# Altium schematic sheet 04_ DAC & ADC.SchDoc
size 420 x 297 mm; SheetNumber: 4; SheetTotal: 4
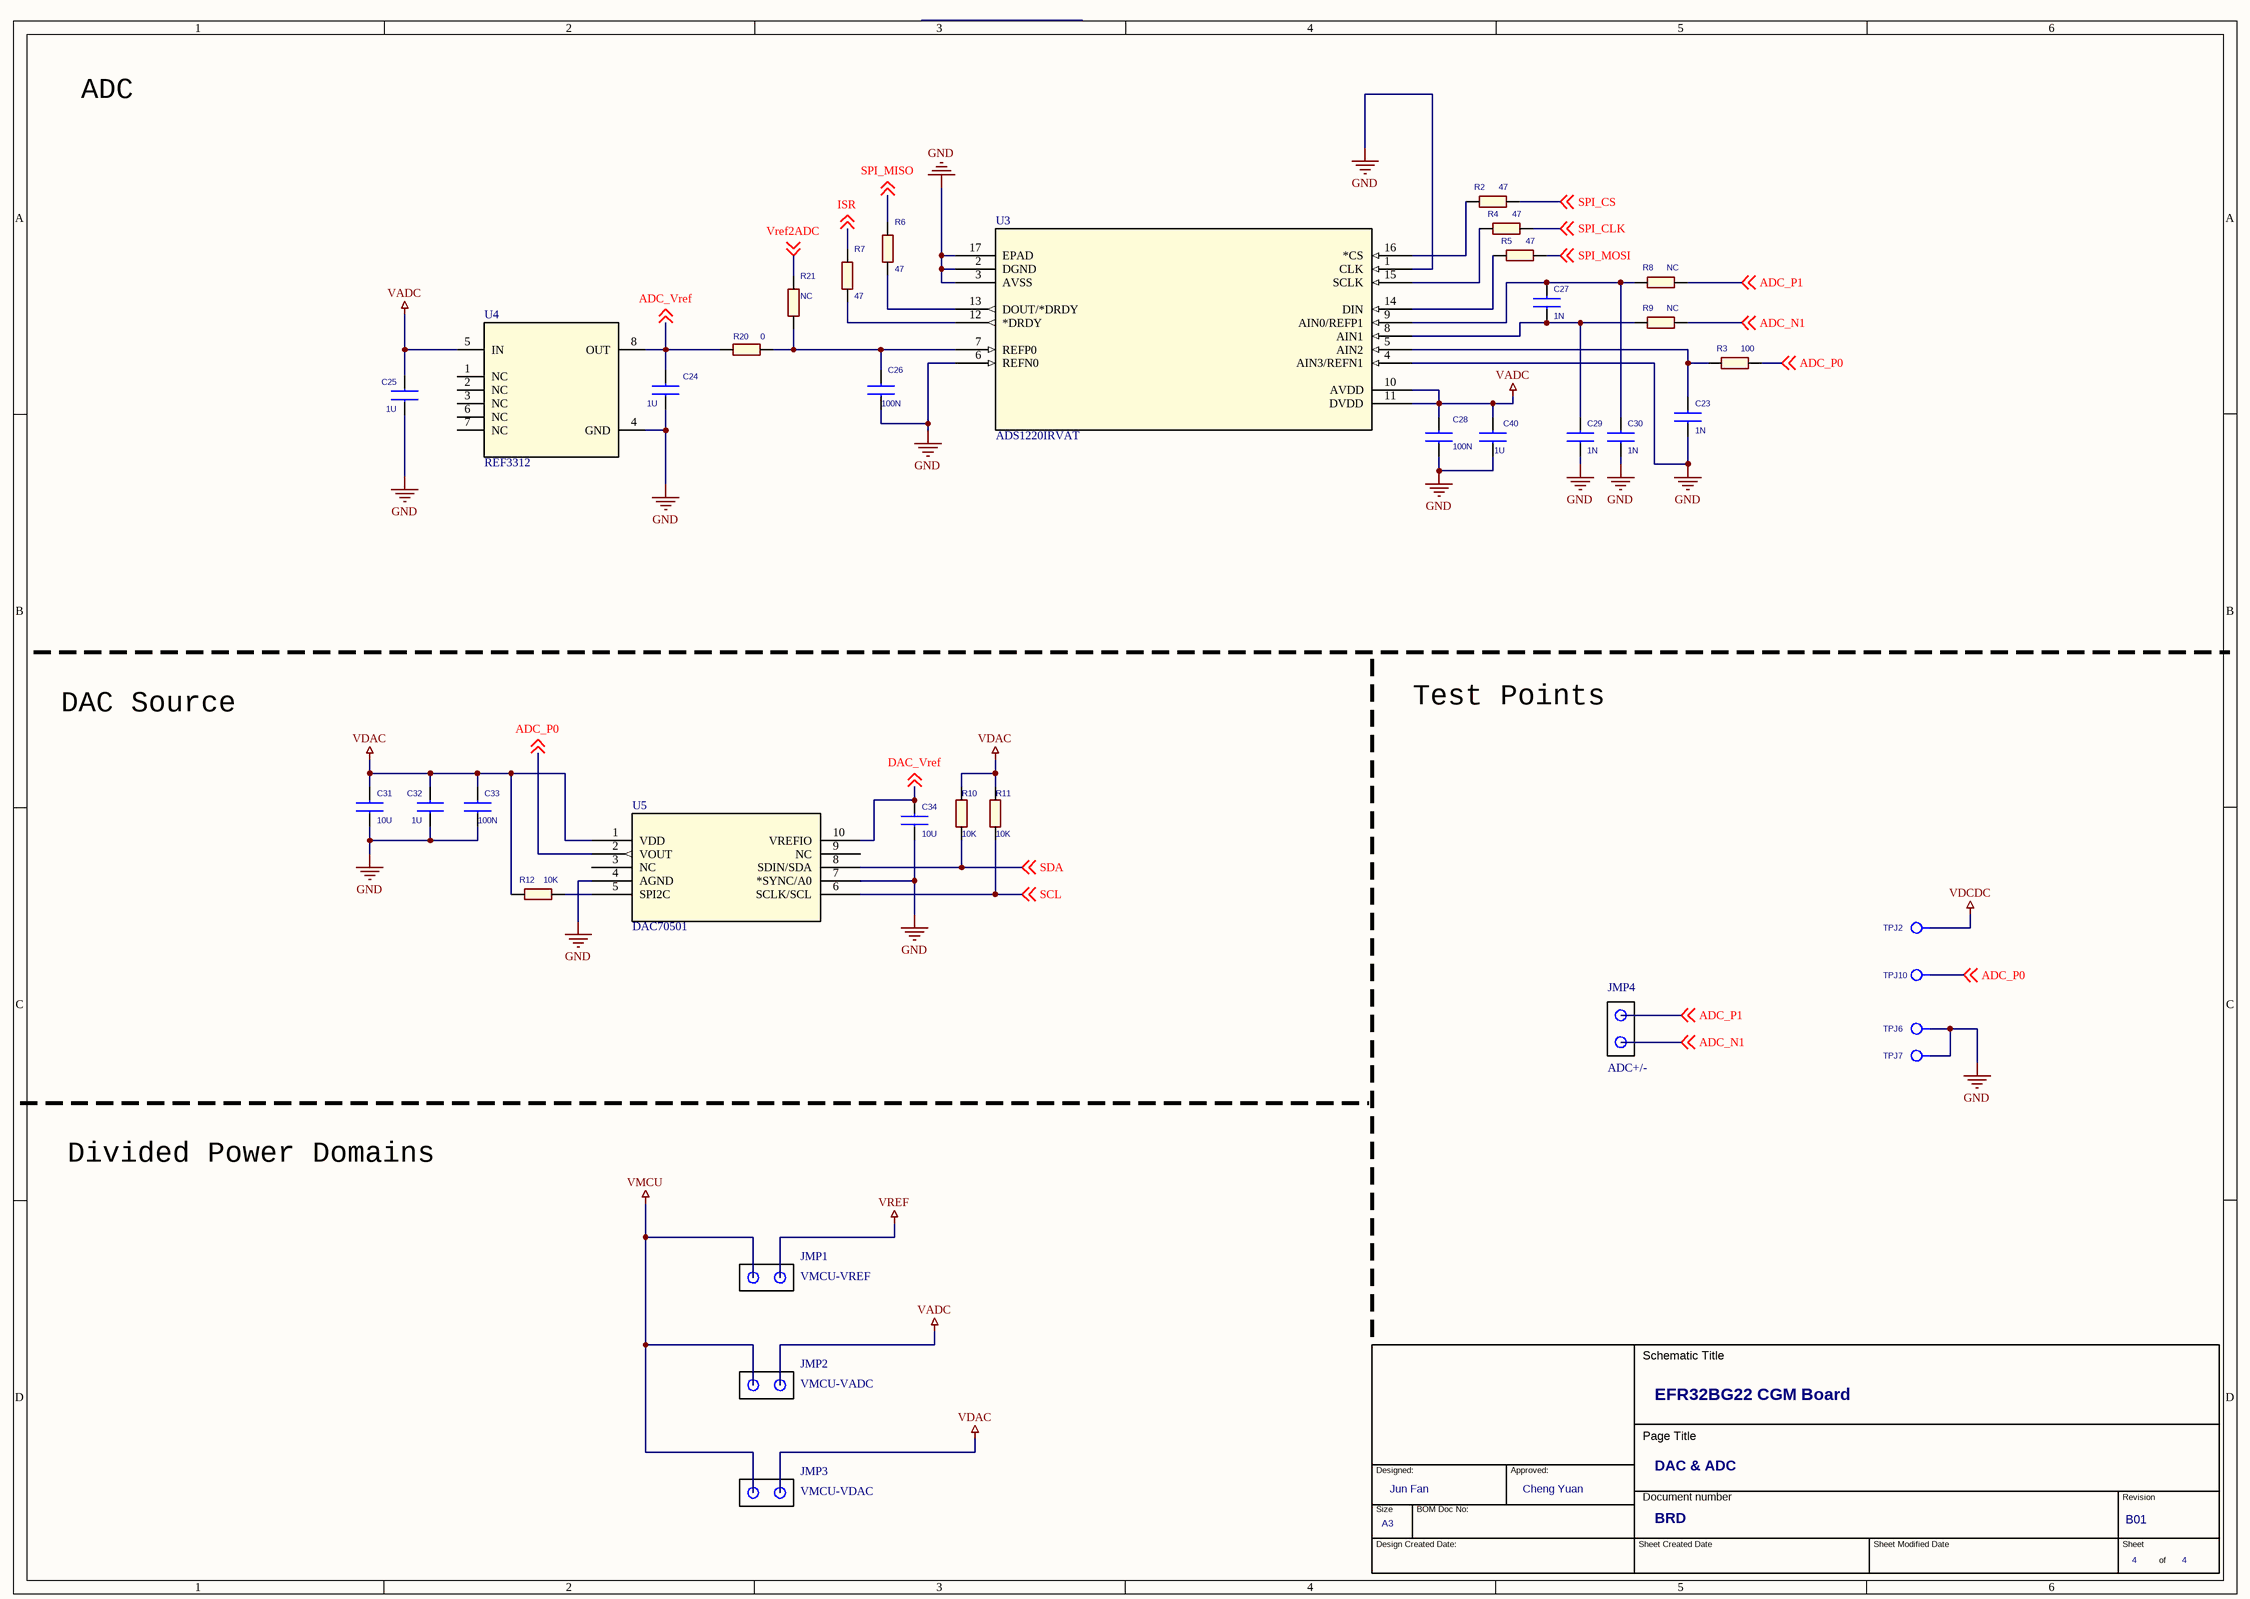
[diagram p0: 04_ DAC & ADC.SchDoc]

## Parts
*?  OrgAddr2: Cheng Yuan  OrgAddr1: Jun Fan  Page Count: 4  Doc: BRD  Title: EFR32BG22 CGM Board  RevCode: B01  Page Size: A3  Page Title: DAC & ADC  (hidden comment: TitleBlock_SiLabs_A3)  (graphical)
C23  1N  [C0201_L]
C24  1U  [C0402_L]
C25  1U  [C0402_L]
C26  100N  [C0201_L]
C27  1N  [C0201_L]
C28  100N  [C0201_L]
C29  1N  [C0201_L]
C30  1N  [C0201_L]
C31  10U  [C0603_L]
C32  1U  [C0402_L]
C33  100N  [C0201_L]
C34  10U  [C0603_L]
C40  1U  [C0402_L]
JMP1  VMCU-VREF  [2Pin-JMP]
JMP2  VMCU-VADC  [2Pin-JMP]
JMP3  VMCU-VDAC  [2Pin-JMP]
JMP4  ADC+/-  [2Pin-JMP]
R2  47  [R0402_L]
R3  100  [R0402_L]
R4  47  [R0402_L]
R5  47  [R0402_L]
R6  47  [R0402_L]
R7  47  [R0402_L]
R8  NC  [R0402_L]
R9  NC  [R0402_L]
R10  10K  [R0402_L]
R11  10K  [R0402_L]
R12  10K  [R0402_L]
R20  0  [R0402_L]
R21  NC  [R0402_L]
TPJ2  VDC  [TP_1.0_SMD]  (value not drawn)
TPJ6  GND  [TP_1.0_SMD]  (value not drawn)
TPJ7  GND  [TP_1.0_SMD]  (value not drawn)
TPJ10  A_P0  [TP_1.0_SMD]  (value not drawn)
U3  ADS1220IRVAT  [RVA16_2P14X2P14]
U4  REF3312  [RSE0008A]
U5  DAC70501  [DGS10_TEX]

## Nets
GND: C23.2 C24.2 C25.2 C26.2 C28.2 C29.2 C30.2 C31.2 C32.2 C33.2 C34.2 C40.2 TPJ6.1(TP) TPJ7.1(TP) U3.1(CLK) U3.2(DGND) U3.3(AVSS) U3.4(AIN3/REFN1) U3.6(REFN0) U3.17(EPAD) U4.4(GND) U5.4(AGND) U5.7(*SYNC/A0)
VADC: C25.1 C28.1 C40.1 JMP2.2(TP) U3.10(AVDD) U3.11(DVDD) U4.5(IN)
VDAC: C31.1 C32.1 C33.1 JMP3.2(TP) R10.1 R11.1 R12.1 U5.1(VDD)
VDCDC: TPJ2.1(TP)
VMCU: JMP1.1(TP) JMP2.1(TP) JMP3.1(TP)
VREF: JMP1.2(TP)
ADC_N1: JMP4.2(TP) R9.2 ; off-sheet ADC_N1
ADC_P0: R3.2 TPJ10.1(TP) U5.2(VOUT) ; off-sheet ADC_P0
ADC_P1: JMP4.1(TP) R8.2 ; off-sheet ADC_P1
ADC_Vref: C24.1 R20.2 U4.8(OUT) ; off-sheet ADC_Vref
DAC_Vref: C34.1 U5.10(VREFIO) ; off-sheet DAC_Vref
ISR: R7.1 ; off-sheet ISR
SCL: R11.2 U5.6(SCLK/SCL) ; off-sheet SCL
SDA: R10.2 U5.8(SDIN/SDA) ; off-sheet SDA
SPI_CLK: R4.2 ; off-sheet SPI_CLK
SPI_CS: R2.2 ; off-sheet SPI_CS
SPI_MISO: R6.1 ; off-sheet SPI_MISO
SPI_MOSI: R5.2 ; off-sheet SPI_MOSI
Vref2ADC: R21.2 ; off-sheet Vref2ADC
NetC23_1: C23.1 R3.1 U3.5(AIN2)
NetC26_1: C26.1 R20.1 R21.1 U3.7(REFP0)
NetC27_1: C27.1 C30.1 R8.1 U3.9(AIN0/REFP1)
NetC27_2: C27.2 C29.1 R9.1 U3.8(AIN1)
NetR2_1: R2.1 U3.16(*CS)
NetR4_1: R4.1 U3.15(SCLK)
NetR5_1: R5.1 U3.14(DIN)
NetR6_2: R6.2 U3.13(DOUT/*DRDY)
NetR7_2: R7.2 U3.12(*DRDY)
NetR12_2: R12.2 U5.5(SPI2C)

Not connected (* = marked no-connect by the designer): U4 1(NC) 2(NC) 3(NC) 6(NC) 7(NC); U5 3(NC) 9(NC)

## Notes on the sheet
- ADC
- DAC Source
- Test Points
- Divided Power Domains

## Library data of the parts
*? = TitleBlock_SiLabs_A3: Cage Code: <Cage Code>
C23 C27 C29 C30 = C0201: Rating: 10V; Tolerance: 10%
C24-C26 C28 C32 C33 C40 = C0201: Rating: 25V; Tolerance: 10%
C31 C34 = C0603: Rating: 25V; Tolerance: 20%
JMP1-JMP4 = JMP-2P
R2-R12 R20 R21 = RESISTOR: Tolerance: 5%
TPJ2 TPJ6 TPJ7 TPJ10 = TPJ_SMD_Dup1
U3 = ADS1220IRVAT: No Description Available; Mfg: Texas Instruments
U4 = REF3312AIRSET: No Description Available; PartNumber: REF3312AIRSER; Mfg: Texas Instruments
U5 = DAC70501MDGST: No Description Available; Built_By: EMA_Molly; SourceLibrary: Texas_Instruments_2019-08-28; Mfg: Texas Instruments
